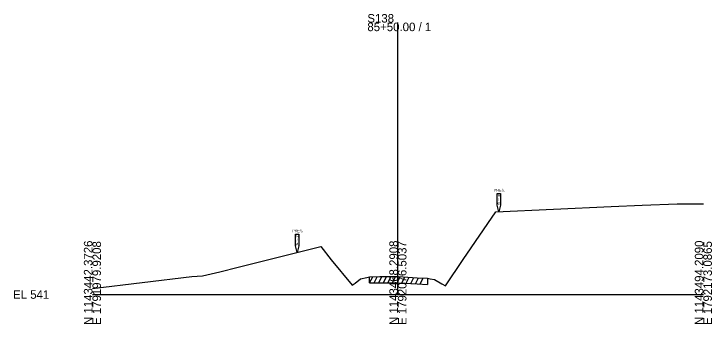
# Model space of a CAD drawing. Extents: x -26 to 1203, y -10 to 19606.
# Drawn here: x -25.7 to 202.8, y 10990.3 to 11092 of the extents above; entities that cross this region are included whole.
import ezdxf

# ---------------------------------------------------------------- set-up
doc = ezdxf.new("R2010")
doc.units = 0
for name, color, linetype in [('RD_EX_Driveway', 7, 'Continuous'), ('RD_GPK_XS_Cell', 7, 'Continuous'), ('RD_XS_ExGround', 7, 'Continuous'), ('RD_XS_ExPaveRet', 7, 'Continuous'), ('RD_XS_ExRW', 7, 'Continuous')]:
    doc.layers.add(name, color=color, linetype=linetype)

msp = doc.modelspace()

# ---------------------------------------------------------------- linework, layer by layer
at = {"layer": 'RD_GPK_XS_Cell'}
for p, q in [((100, 11000), (100, 11089.16)), ((0, 11000), (100, 11000)), ((100, 11000), (200, 11000))]:
    msp.add_line(p, q, dxfattribs=at)
at = {"layer": 'RD_XS_ExGround'}
msp.add_lwpolyline([(0, 11001.96), (32.59, 11005.95), (36.04, 11006.14), (41.65, 11007.47), (47.66, 11008.96), (74.8, 11015.73), (78.14, 11011.41), (85.02, 11003.02), (86, 11003.77), (87.74, 11005.13), (89.78, 11005.59), (90.75, 11005.8), (94.08, 11005.85), (100.19, 11005.86), (106.35, 11005.49), (109.68, 11005.33), (110.56, 11005.17), (111.95, 11004.96), (114.41, 11003.52), (115.58, 11002.81), (121.35, 11011.47), (132.08, 11027.09), (169.84, 11028.83), (179.96, 11029.29), (191.47, 11029.71), (200, 11029.72)], dxfattribs=at)
at = {"layer": 'RD_XS_ExPaveRet'}
for p, q in [((90.75, 11003.8), (91.76, 11005.81)), ((90.75, 11003.8), (90.75, 11005.8)), ((90.75, 11003.8), (94.08, 11003.85)), ((92.25, 11003.82), (93.26, 11005.84)), ((93.75, 11003.85), (94.76, 11005.85)), ((94.08, 11003.85), (100.19, 11003.86)), ((95.25, 11003.85), (96.26, 11005.85)), ((96.75, 11003.86), (97.76, 11005.86)), ((98.25, 11003.86), (99.26, 11005.86)), ((99.75, 11003.86), (100.74, 11005.83)), ((100.19, 11003.86), (106.35, 11003.49)), ((101.25, 11003.8), (102.23, 11005.74)), ((102.75, 11003.71), (103.73, 11005.65)), ((104.25, 11003.62), (105.23, 11005.56)), ((105.75, 11003.53), (106.73, 11005.47)), ((107.25, 11003.45), (108.23, 11005.4)), ((109.68, 11005.33), (109.68, 11003.33)), ((106.35, 11003.49), (109.68, 11003.33))]:
    msp.add_line(p, q, dxfattribs=at)
at = {"layer": 'RD_XS_ExRW'}
for points in [[(132.45, 11033.14), (133.55, 11033.14), (133.55, 11029.32), (133, 11027.13), (132.45, 11029.32)], [(66.45, 11019.8), (67.55, 11019.8), (67.55, 11015.98), (67, 11013.79), (66.45, 11015.98)]]:
    msp.add_lwpolyline(points, close=True, dxfattribs=at)

# ---------------------------------------------------------------- texts
at = {"layer": 'RD_EX_Driveway'}
msp.add_text('543.93', height=0.0975, rotation=90, dxfattribs=at).set_placement((100.1, 11005.86))
at = {"layer": 'RD_GPK_XS_Cell'}
for s, p in [('S138', (90, 11089.16)), ('85+50.00 / 1', (90, 11086.36)), ('EL 541', (-26, 10998.6))]:
    msp.add_text(s, height=2.8, dxfattribs=at).set_placement(p)
for s, p in [('N 1143442.3726', (0, 10990)), ('E 1791979.9208', (2.8, 10990)), ('N 1143468.2908', (100, 10990)), ('E 1792076.5037', (102.8, 10990)), ('N 1143494.2090', (200, 10990)), ('E 1792173.0865', (202.8, 10990))]:
    msp.add_text(s, height=2.8, rotation=90, dxfattribs=at).set_placement(p)
at = {"layer": 'RD_XS_ExRW'}
for s, p in [('PRES.', (131.45, 11033.77)), ('R', (132.71, 11032.05)), ('/', (132.83, 11030.74)), ('W', (132.53, 11029.43)), ('PRES.', (65.45, 11020.43)), ('R', (66.71, 11018.71)), ('/', (66.83, 11017.4)), ('W', (66.53, 11016.09))]:
    msp.add_text(s, height=0.875, dxfattribs=at).set_placement(p)

doc.saveas('drawing.dxf')
